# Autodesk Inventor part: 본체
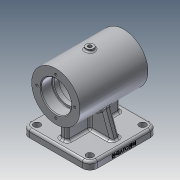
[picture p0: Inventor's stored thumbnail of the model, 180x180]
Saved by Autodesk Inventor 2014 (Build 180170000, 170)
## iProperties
Created: 2019-06
Part Number: 본체
Material: 알루미늄 6061
Document SubType Name: Modeling
Designer: net
Density: 2.71 g/cm^3
Appearance: 알루미늄 - 평지
Mass: 611.033 g
Surface Area: 626.842 cm^2
Volume: 225.474 cm^3
Author: net
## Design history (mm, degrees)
sketch "스케치1"
  geometry: L1 (-45, 0)-(45, 0); L2 (-45, 0)-(-45, 20); L3 (-45, 20)-(-45, 32); L4 (-45, 32)-(45, 32); L5 (45, 32)-(45, 20); L6 (45, 20)-(45, 0); L7 (45, 20)-(30, 20); L8 (30, 20)-(30, 17); L9 (30, 17)-(24, 17); L10 (24, 17)-(24, 25); L11 (24, 25)-(-24, 25); L12 (-24, 25)-(-24, 17); L13 (-24, 17)-(-30, 17); L14 (-30, 17)-(-30, 20); L15 (-30, 20)-(-45, 20); 1 further point
  constraints: 31 end point, 8 parallel, 5 perpendicular, 1 collinear, 1 horizontal, 1 midpoint
  dimensions: "d0" = 90 distance of L1.start L1.end; "d1" = 45 distance of L1.end point (0, 0); "d2" = 34 diameter of L13 L1; "d3" = 50 diameter of L11 L1; "d4" = 40 diameter of L7 L1; "d5" = 34 diameter of L9 L1; "d6" = 40 diameter of L15 L1; "d7" = 64 diameter of L4 L1; "d8" = 15 distance between parallel lines of L2 L14; "d9" = 48 distance between parallel lines of L10 L12; "d11" = 15 distance between parallel lines of L6 L8; "d12" = 24 horizontal distance of point (0, 0) L10.end
revolve "회전1" sketch "스케치1" stored, may be unused: angle "d13" = 90 deg
sketch "스케치2"
  geometry: L1 (0, 0)-(0, -65); L2 (0, -65)-(45, -65); L3 (45, -65)-(45, -55); L4 (45, -55)-(-45, -55); L5 (0, -65)-(-45, -65); L6 (-45, -65)-(-45, -55)
  constraints: 12 end point, 3 perpendicular, 2 parallel, 1 vertical
  dimensions: "d14" = 65 distance of L1.start L1.end; "d15" = 10 distance of L2.end L3.end; "d16" = 90 distance of L3.end L4.end; "d17" = 45 distance of L5.end L1.end
extrude "돌출1" join sketch "스케치2" stored distance "d18" = 90; taper "d19" = 0 deg
sketch "스케치3"
  geometry: L1 (0, 0)-(0, -27.268); L2 (-45, -55)-(45, -55) reference; L3 (0, -27.268)-(0, -55); L4 (0, -27.268)-(-35, -27.268); L5 (-35, -27.268)-(-35, -55); L6 (0, -55)-(-35, -55); L7 (0, -27.268)-(35, -27.268); L8 (35, -27.268)-(35, -55); L9 (0, -55)-(35, -55)
  constraints: 16 end point, 3 perpendicular, 2 collinear, 2 point on line, 1 midpoint, 1 parallel, 1 vertical
  dimensions: "d20" = 35 distance of L1.end L4.end; "d21" = 35 distance of L1.end L7.end; "d22" = 27.26751 distance of L1.start L1.end
extrude "돌출2" join sketch "스케치3" stored distance "d23" = 10; taper "d24" = 0 deg
sketch "스케치4"
  geometry: 1 further point
sketch "스케치5"
  geometry: L1 (45, -55)-(-45, -55) reference; L2 (35, -55)-(23.058, -22.189); L3 (-23.058, -22.189)-(-35, -55); A1 r 32 centre (0, 0) between (23.058, -22.189) and (-23.058, -22.189) reference; 1 further point
  constraints: 4 end point, 2 point on circle, 2 point on line
  dimensions: "d25" = 10 distance of L1.start L2.start; "d26" = 10 distance of L1.end L3.end; "d27" = 110 deg angle of L1 L3; "d28" = 110 deg angle of L1 L2
feature "리브1" dims "d29" = 1, "d30" = 10, "d31" = 0, "d32" = 0, "d33" = 1, "d34" = 1
feature "리브2" dims "d35" = 1, "d36" = 10, "d37" = 0, "d38" = 0, "d39" = 1, "d40" = 1
fillet "모깎기1" dims "d41" = 3
sketch "스케치6"
  geometry: C1 r 20 at (0, 0) reference; C2 r 32 at (0, 0) reference; A1 r 25 centre (0, 0) between (0, 25) and (25, 0); 2 further points
  constraints: 4 point on circle, 2 horizontal alignment, 2 vertical alignment, 1 centre point, 1 coincident
  dimensions: "d42" = 50 diameter of A1
hole "구멍1" sketch "스케치6" at (0, 25), (25, 0), (0, -25), (-25, 0) diameter "d43" = 3.242; stored, may be unused: countersink angle "d47" = 90 deg, drill point angle "d49" = 118 deg; dims "d44" = 7, "d45" = 4, "d46" = 2, "d48" = 9
sketch "스케치7"
  geometry: C1 r 1.621 at (0, -25) reference; C2 r 1.621 at (-25, 0) reference; C3 r 1.621 at (0, 25) reference; C4 r 1.621 at (25, 0) reference; 4 further points
  constraints: 4 coincident
hole "구멍2" sketch "스케치7" at (0, -25), (-25, 0), (0, 25), (25, 0) diameter "d50" = 3.242; stored, may be unused: countersink angle "d54" = 90 deg, drill point angle "d56" = 118 deg; dims "d51" = 7, "d52" = 4, "d53" = 2, "d55" = 9
sketch "스케치8"
  geometry: L1 (0, 0)-(0, 35); L2 (-45, 32)-(45, 32) reference
  constraints: 2 end point, 1 vertical
  dimensions: "d57" = 3 distance from line of L2 L1.end
node "작업 평면1"
sketch "스케치9"
  geometry: C1 r 5 at (0, 0); 1 further point
  constraints: 1 centre point, 1 coincident
  dimensions: "d58" = 10 diameter of C1
extrude "돌출3" join sketch "스케치9" distance "d59" = 6; taper "d60" = 0 deg
sketch "스케치10"
  geometry: C1 r 5 at (0, 0) reference
hole "구멍3" sketch "스케치10" at (0, 0) diameter "d61" = 4.917; stored, may be unused: countersink angle "d65" = 90 deg, drill point angle "d67" = 118 deg; dims "d62" = 14, "d63" = 4, "d64" = 2, "d66" = 15
sketch "스케치12"
  geometry: L1 (0, 0)-(90, 0) reference; L2 (0, -90)-(0, 0) reference; C1 r 4.5 at (10, -10); C2 r 4.5 at (80, -10); C3 r 4.5 at (10, -80); C4 r 4.5 at (80, -80); 1 further point
  constraints: 4 centre point, 1 horizontal, 1 vertical, 6 other
  dimensions: "d68" = 9 diameter of C1; "d69" = 10 distance from line of L2 C1.centre; "d70" = 10 distance from line of L1 C1.centre; "d73" = 70 distance of C1.centre C2.centre; "d76" = 70 distance of C1.centre C3.centre
extrude "돌출4" cut sketch "스케치12" stored distance "d79" = 6; taper "d80" = 0 deg
sketch "스케치13"
  geometry: L1 (90, 0)-(0, 0) reference; L2 (90, 90)-(0, 90) reference; L3 (5, 5)-(18.66, 5); L4 (85, 5)-(85, 18.66); L5 (85, 85)-(71.34, 85); L6 (5, 85)-(5, 71.34); L7 (5, 5)-(85, 85); L8 (85, 5)-(5, 85); L9 (5, 18.66)-(5, 5); L10 (18.66, 5)-(71.34, 5); L11 (71.34, 85)-(18.66, 85); L12 (85, 71.34)-(85, 85); L13 (18.66, 85)-(5, 85); L14 (5, 71.34)-(5, 18.66); L15 (85, 18.66)-(85, 71.34); L16 (71.34, 5)-(85, 5); C1 r 4.5 at (80, 10) reference; C2 r 4.5 at (80, 80) reference; C3 r 4.5 at (10, 80) reference; C4 r 4.5 at (10, 10) reference; A1 r 10 centre (10, 80) between (10, 90) and (5, 71.34); A2 r 10 centre (80, 10) between (80, 0) and (85, 18.66); A3 r 10 centre (10, 10) between (5, 18.66) and (18.66, 5); A4 r 10 centre (10, 80) between (18.66, 85) and (10, 90); A5 r 10 centre (10, 80) between (5, 71.34) and (18.66, 85); A6 r 10 centre (80, 10) between (71.34, 5) and (80, 0); A7 r 10 centre (80, 10) between (85, 18.66) and (71.34, 5); A8 r 10 centre (10, 10) between (17.071, 17.071) and (5, 18.66); A9 r 10 centre (10, 10) between (18.66, 5) and (17.071, 17.071); A10 r 10 centre (80, 80) between (71.34, 85) and (85, 71.34); A11 r 10 centre (80, 80) between (80, 90) and (71.34, 85); A12 r 10 centre (80, 80) between (85, 71.34) and (80, 90); 1 further point
  constraints: 28 end point, 24 point on circle, 18 parallel, 12 centre point, 9 perpendicular, 5 point on line, 4 coincident, 3 horizontal, 2 midpoint, 1 equal radius
  dimensions: "d81" = 80 distance of L6.start L3.start; "d82" = 80 distance of L5.start L6.start; "d84" = 20 diameter of A1; "d87" = 20 diameter of A10; "d88" = 10 radius of A7
extrude "돌출5" cut sketch "스케치13" distance "d89" = 5; taper "d90" = 0 deg
fillet "모깎기2" dims "d91" = 2
fillet "모깎기3" dims "d92" = 3
chamfer "모따기1" distance "d93" = 1; stored, may be unused: second distance "d94" = 2, angle "d95" = 45 deg
fillet "모깎기4" dims "d96" = 0.6
fillet "모깎기5" dims "d97" = 3
fillet "모깎기6" dims "d98" = 3
fillet "모깎기7" dims "d99" = 3
fillet "모깎기8" dims "d100" = 10
fillet "모깎기9" dims "d101" = 3
node "작업 평면2"
sketch "스케치14"
  geometry: L1 (45, -65)-(45, -58) reference; L2 (-35, -65)-(35, -65) reference; 2 further points
  constraints: 1 other
  dimensions: "d103" = 45 distance from line of L1 point (0, -61); "d104" = 4 distance from line of L2 point (0, -61)
feature "엠보싱1" sketch "스케치14" dims "d0" = 90, "d1" = 45, "d2" = 34, "d3" = 50, "d4" = 40, "d5" = 34, "d6" = 40, "d7" = 64, "d8" = 15, "d9" = 48, "d11" = 15, "d12" = 24, "d37" = 0, "d74" = 20, "d105" = 0.5, "d106" = 0
node "솔리드1"
other parameters: "d102" = 48.75
